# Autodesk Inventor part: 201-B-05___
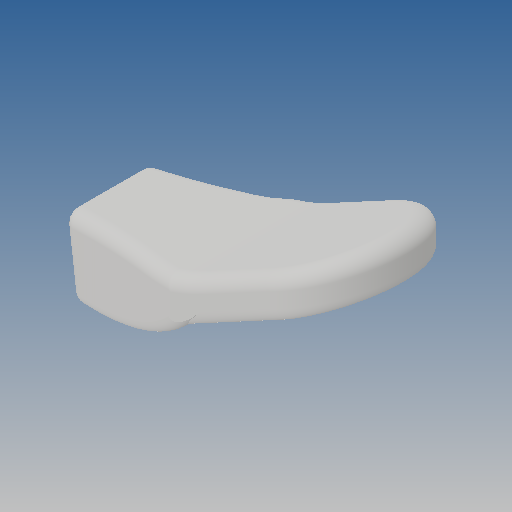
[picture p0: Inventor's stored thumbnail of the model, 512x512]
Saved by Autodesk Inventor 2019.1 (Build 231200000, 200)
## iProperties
Created: 2010-06
Part Number: 201-B-05___
Material: Ogólny
Document SubType Name: Modeling
Designer: CADENGINEERING4
Density: 1 g/cm^3
Appearance: Domyślna
Author: CADENGINEERING4
Revision Number: ANY
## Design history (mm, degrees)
feature "NONE"
node "Bryła1"
